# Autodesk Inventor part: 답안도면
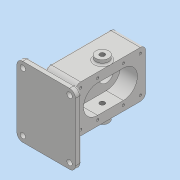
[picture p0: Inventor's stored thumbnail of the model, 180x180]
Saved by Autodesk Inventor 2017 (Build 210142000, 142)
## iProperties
Part Number: 답안도면
Material: 일반
Document SubType Name: Modeling
Designer: MRC
Density: 1 g/cm^3
Appearance: 기본값
Author: MRC
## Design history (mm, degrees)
sketch "스케치1"
  geometry: L1 (-26.5, 60)-(-26.5, -60); L2 (-26.5, -60)-(26.5, -60); L3 (-26.5, 60)-(26.5, 60); L4 (26.5, 60)-(26.5, -60); 3 further points
  constraints: 8 end point, 2 horizontal, 2 midpoint, 1 horizontal alignment, 1 vertical, 1 vertical alignment
  dimensions: "d0" = 120 distance of L1.start L1.end; "d1" = 53 distance of L1.end L2.end; "d2" = 53 distance of L1.start L3.end
extrude "돌출1" new body sketch "스케치1" stored distance "d3" = 80; taper "d4" = 0 deg
sketch "스케치2"
  geometry: L1 (40, 60)-(40, 82); L2 (40, 60)-(40, 38); L3 (40, 82)-(40, 38); L4 (16, 82)-(16, 38); L5 (64, 38)-(64, 82); A1 r 24 centre (40, 82) between (64, 82) and (16, 82); A2 r 24 centre (40, 38) between (16, 38) and (64, 38); 1 further point
  constraints: 12 end point, 4 point on circle, 4 tangent, 3 vertical, 2 centre point, 1 midpoint, 1 parallel
  dimensions: "d5" = 22 distance of L1.start L1.end; "d6" = 22 distance of L1.start L2.end; "d7" = 48 diameter of A2
extrude "돌출2" cut sketch "스케치2" distance "d8" = 29; taper "d9" = 0 deg
sketch "스케치3"
  geometry: C1 r 12.5 at (40, 82); C2 r 12.5 at (40, 38); A1 r 24 centre (40, 38) between (16, 38) and (64, 38) reference; A2 r 24 centre (40, 82) between (64, 82) and (16, 82) reference; 1 further point
  constraints: 2 centre point, 2 coincident
  dimensions: "d10" = 25 diameter of C1; "d11" = 25 diameter of C2
extrude "돌출3" cut sketch "스케치3" distance "d12" = 15; taper "d13" = 0 deg
sketch "스케치4"
  geometry: L1 (-40, 60)-(-40, 82); C1 r 19 at (-40, 82)
  constraints: 2 end point, 1 centre point, 1 coincident, 1 vertical
  dimensions: "d14" = 22 distance of L1.start L1.end; "d15" = 38 diameter of C1
extrude "돌출4" join sketch "스케치4" distance "d16" = 17; taper "d17" = 0 deg
sketch "스케치5"
  geometry: C1 r 19 at (0, 0) reference; C2 r 14 at (0, 0); 1 further point
  constraints: 1 centre point, 1 coincident
  dimensions: "d18" = 28 diameter of C2
extrude "돌출5" cut sketch "스케치5" distance "d19" = 7.3; taper "d20" = 0 deg
sketch "스케치6"
  geometry: C1 r 12.5 at (0, 0) reference; C2 r 8.5 at (0, 0); 1 further point
  constraints: 1 centre point, 1 coincident
  dimensions: "d21" = 17 diameter of C2
extrude "돌출6" cut sketch "스케치6" distance "d22" = 18.7; taper "d23" = 0 deg
node "작업 평면1"
sketch "스케치7"
  geometry: L1 (-56.5, -60)-(43.5, -60); L2 (43.5, -60)-(43.5, 60); L3 (43.5, 60)-(-56.5, 60); L4 (-56.5, 60)-(-56.5, -60); L5 (43.5, -19)-(43.5, 19) reference; 3 further points
  constraints: 8 end point, 3 midpoint, 2 parallel, 1 horizontal, 1 horizontal alignment, 1 perpendicular
  dimensions: "d25" = 100 distance of L3.end L2.end; "d26" = 120 distance of L2.end L1.end
extrude "돌출7" join sketch "스케치7" distance "d27" = 10; taper "d28" = 0 deg
fillet "모깎기1" dims "d33" = 9
fillet "모깎기2" dims "d34" = 3
sketch "스케치9"
  geometry: L1 (-26.5, -80)-(-14.953, -60); L2 (26.5, -80)-(14.953, -60); L3 (-43.5, -80)-(56.5, -80) reference; L4 (-43.5, -90)-(-43.5, -80) reference; L5 (-23.5, -60)-(26.5, -60) reference; 1 further point
  constraints: 4 end point, 4 point on line
  dimensions: "d35" = 60 deg angle of L1 L3; "d36" = 60 deg angle of L3 L2; "d37" = 17 distance from line of L1.start L4; "d38" = 53 distance of L2.start L1.start
extrude "돌출8" join sketch "스케치9" stored distance "d39" = 48; taper "d40" = 0 deg
sketch "스케치10"
  geometry: L1 (-26.5, 51)-(-26.5, -51) reference; C1 r 11 at (-12.5, 0); 1 further point
  constraints: 1 centre point, 1 horizontal alignment
  dimensions: "d41" = 22 diameter of C1; "d42" = 14 distance from line of C1.centre L1
extrude "돌출9" join sketch "스케치10" distance "d43" = 8; taper "d44" = 0 deg
hole "구멍1" diameter "d47" = 8.376; stored, may be unused: countersink angle "d51" = 90 deg, drill point angle "d53" = 118 deg; dims "d45" = 10, "d46" = 10, "d48" = 20, "d49" = 4, "d50" = 2, "d52" = 27.3
fillet "모깎기3" dims "d54" = 3
fillet "모깎기4" dims "d55" = 10
fillet "모깎기5" dims "d56" = 3
sketch "스케치11"
  geometry: A1 r 7 centre (-33.5, -50) between (-40.5, -50) and (-33.5, -57) reference; A2 r 7 centre (46.5, -50) between (46.5, -57) and (53.5, -50) reference; A3 r 7 centre (46.5, 50) between (53.5, 50) and (46.5, 57) reference; A4 r 7 centre (-33.5, 50) between (-33.5, 57) and (-40.5, 50) reference; 5 further points
  constraints: 4 coincident
hole "구멍2" sketch "스케치11" at (-33.5, 50), (46.5, 50), (46.5, -50), (-33.5, -50) diameter "d57" = 9; stored, may be unused: countersink angle "d61" = 90 deg, drill point angle "d63" = 118 deg; dims "d58" = 20, "d59" = 4, "d60" = 2, "d62" = 27.3
chamfer "모따기1" distance "d64" = 0.7; stored, may be unused: second distance "d65" = 2, angle "d66" = 30 deg
chamfer "모따기2" distance "d67" = 1; stored, may be unused: second distance "d68" = 2, angle "d69" = 30 deg
sketch "스케치12"
  geometry: L1 (-33.5, -60)-(46.5, -60) reference; L2 (56.5, -50)-(56.5, 50) reference; 2 further points
  constraints: 1 other
  dimensions: "d70" = 60 distance from line of L1 point (46.5, 0); "d71" = 10 distance from line of L2 point (46.5, 0)
feature "엠보싱1" sketch "스케치12" dims "d0" = 120, "d1" = 53, "d2" = 53, "d72" = 0.5, "d73" = 0
sketch "스케치13"
  geometry: A1 r 9 centre (62, -111) between (62, -120) and (71, -111) reference; A2 r 9 centre (62, -9) between (71, -9) and (62, 0) reference; A3 r 9 centre (0, -9) between (0, 0) and (-9, -9) reference; A4 r 9 centre (0, -111) between (-9, -111) and (0, -120) reference; 9 further points
  constraints: 4 coincident, 4 vertical alignment, 2 horizontal alignment
  dimensions: "d74" = 29 distance of point (0, -38) point (0, -9); "d75" = 29 distance of point (0, -111) point (0, -82)
hole "구멍3" sketch "스케치13" at (0, -9), (62, -9), (0, -111), (62, -111), (0, -38), (0, -82), (62, -38), (62, -82) diameter "d76" = 4.134; stored, may be unused: countersink angle "d80" = 90 deg, drill point angle "d82" = 118 deg; dims "d77" = 10, "d78" = 4, "d79" = 2, "d81" = 12
chamfer "모따기3" distance "d83" = 0.5; stored, may be unused: second distance "d84" = 2, angle "d85" = 30 deg
node "솔리드1"
mirror "미러1"
